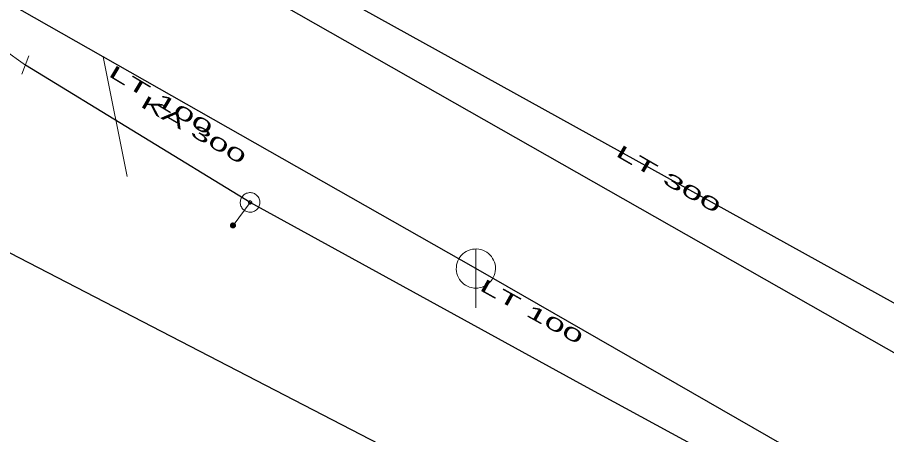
# Model space of a CAD drawing. Extents: x -687593 to -687108, y -975254 to -974717.
# Drawn here: x -687397.23 to -687352.84, y -974948.69 to -974927.39 of the extents above; entities that cross this region are included whole.
import ezdxf
from ezdxf.enums import TextEntityAlignment as Align

# ---------------------------------------------------------------- set-up
doc = ezdxf.new("R2010")
doc.units = 0
doc.header["$LTSCALE"] = 0.27
for name, color, linetype, lineweight in [('1', 7, 'Continuous', 25), ('11', 7, 'Continuous', 13), ('14', 7, 'Continuous', 13), ('17', 7, 'Continuous', 25), ('22', 7, 'Continuous', 13), ('34', 7, 'Continuous', 13), ('47', 7, 'Continuous', 13), ('9', 7, 'Continuous', 13)]:
    doc.layers.add(name, color=color, linetype=linetype, lineweight=lineweight)

msp = doc.modelspace()

# ---------------------------------------------------------------- linework, layer by layer
at = {"layer": '1'}
msp.add_lwpolyline([(-687190.553, -975166.941), (-687164.86, -975177.861), (-687155.924, -975158.837), (-687125.348, -975155.541), (-687124.826, -975139.621), (-687173.065, -975131.89), (-687231.828, -975028.025), (-687222.959, -975015.464), (-687237.898, -975004.026), (-687247.4, -975009.654), (-687276.892, -974983.781), (-687453.606, -974886.044), (-687460.232, -974860.45), (-687474.874, -974858.564), (-687482.889, -974882.272), (-687502.421, -974882.802), (-687499.452, -974907.164), (-687464.42, -974904.824), (-687331.319, -974973.728), (-687252.566, -975037.916), (-687192.379, -975151.48)], close=True, dxfattribs=at)
at = {"layer": '11'}
msp.add_line((-687391.62, -974935.51), (-687392.845, -974929.413), dxfattribs=at)
at = {"layer": '14'}
for p, q in [((-687396.817, -974929.825), (-687397.965, -974929.018)), ((-687385.348, -974936.838), (-687386.22, -974938.013))]:
    msp.add_line(p, q, dxfattribs=at)
at = {"layer": '14', "lineweight": 25}
msp.add_line((-687339.967, -974959.63), (-687373.818, -974940.214), dxfattribs=at)
msp.add_lwpolyline([(-687373.818, -974940.214), (-687392.845, -974929.413), (-687401.895, -974924.263)], dxfattribs=at)
at = {"layer": '17'}
for points in [[(-687435.81, -974897.134), (-687294.34, -974977.541), (-687214.33, -974877.654)], [(-687358.699, -974951.407), (-687368.317, -974946.193), (-687385.348, -974936.838), (-687396.817, -974929.825)]]:
    msp.add_lwpolyline(points, dxfattribs=at)
at = {"layer": '22'}
msp.add_line((-687373.818, -974942.214), (-687373.817, -974939.214), dxfattribs=at)
msp.add_lwpolyline([(-687372.818, -974940.214), (-687372.823, -974940.105), (-687372.841, -974939.997), (-687372.871, -974939.891), (-687372.911, -974939.79), (-687372.963, -974939.693), (-687373.025, -974939.603), (-687373.097, -974939.52), (-687373.177, -974939.446), (-687373.265, -974939.38), (-687373.359, -974939.325), (-687373.459, -974939.28), (-687373.564, -974939.247), (-687373.671, -974939.225), (-687373.78, -974939.215), (-687373.89, -974939.217), (-687373.998, -974939.231), (-687374.105, -974939.256), (-687374.208, -974939.293), (-687374.306, -974939.342), (-687374.398, -974939.4), (-687374.484, -974939.469), (-687374.561, -974939.546), (-687374.63, -974939.632), (-687374.689, -974939.724), (-687374.737, -974939.822), (-687374.774, -974939.925), (-687374.8, -974940.032), (-687374.814, -974940.14), (-687374.817, -974940.25), (-687374.807, -974940.359), (-687374.786, -974940.466), (-687374.752, -974940.57), (-687374.708, -974940.67), (-687374.653, -974940.765), (-687374.587, -974940.853), (-687374.513, -974940.933), (-687374.43, -974941.005), (-687374.34, -974941.067), (-687374.244, -974941.119), (-687374.142, -974941.16), (-687374.037, -974941.19), (-687373.929, -974941.208), (-687373.819, -974941.214), (-687373.71, -974941.208), (-687373.602, -974941.19), (-687373.497, -974941.161), (-687373.395, -974941.12), (-687373.298, -974941.068), (-687373.208, -974941.006), (-687373.125, -974940.935), (-687373.05, -974940.855), (-687372.985, -974940.767), (-687372.929, -974940.673), (-687372.885, -974940.573), (-687372.851, -974940.469), (-687372.829, -974940.361), (-687372.819, -974940.252)], close=True, dxfattribs=at)
at = {"layer": '34'}
msp.add_line((-687396.638, -974929.357), (-687396.996, -974930.291), dxfattribs=at)
at = {"layer": '47'}
for points in [[(-687384.924, -974937.104), (-687384.899, -974937.058), (-687384.878, -974937.01), (-687384.863, -974936.96), (-687384.853, -974936.909), (-687384.848, -974936.856), (-687384.849, -974936.804), (-687384.856, -974936.752), (-687384.867, -974936.701), (-687384.884, -974936.652), (-687384.905, -974936.604), (-687384.932, -974936.559), (-687384.964, -974936.517), (-687384.999, -974936.479), (-687385.039, -974936.445), (-687385.081, -974936.414), (-687385.127, -974936.389), (-687385.175, -974936.368), (-687385.226, -974936.353), (-687385.276, -974936.343), (-687385.329, -974936.338), (-687385.381, -974936.339), (-687385.434, -974936.345), (-687385.485, -974936.357), (-687385.534, -974936.373), (-687385.581, -974936.395), (-687385.626, -974936.422), (-687385.668, -974936.454), (-687385.706, -974936.489), (-687385.74, -974936.529), (-687385.771, -974936.571), (-687385.796, -974936.617), (-687385.817, -974936.665), (-687385.833, -974936.715), (-687385.842, -974936.766), (-687385.847, -974936.819), (-687385.847, -974936.871), (-687385.841, -974936.923), (-687385.829, -974936.974), (-687385.812, -974937.024), (-687385.79, -974937.071), (-687385.763, -974937.116), (-687385.732, -974937.158), (-687385.696, -974937.196), (-687385.656, -974937.23), (-687385.614, -974937.261), (-687385.568, -974937.286), (-687385.52, -974937.307), (-687385.471, -974937.322), (-687385.419, -974937.332), (-687385.366, -974937.337), (-687385.314, -974937.337), (-687385.263, -974937.33), (-687385.212, -974937.319), (-687385.162, -974937.301), (-687385.114, -974937.28), (-687385.069, -974937.253), (-687385.028, -974937.222), (-687384.989, -974937.186), (-687384.955, -974937.146)], [(-687385.278, -974936.881), (-687385.273, -974936.874), (-687385.271, -974936.866), (-687385.268, -974936.858), (-687385.266, -974936.85), (-687385.266, -974936.841), (-687385.266, -974936.832), (-687385.267, -974936.823), (-687385.268, -974936.815), (-687385.272, -974936.807), (-687385.275, -974936.799), (-687385.28, -974936.792), (-687385.285, -974936.785), (-687385.291, -974936.779), (-687385.296, -974936.773), (-687385.304, -974936.768), (-687385.311, -974936.763), (-687385.319, -974936.761), (-687385.327, -974936.758), (-687385.335, -974936.756), (-687385.344, -974936.756), (-687385.353, -974936.756), (-687385.362, -974936.757), (-687385.37, -974936.758), (-687385.379, -974936.761), (-687385.386, -974936.765), (-687385.393, -974936.77), (-687385.4, -974936.775), (-687385.406, -974936.781), (-687385.412, -974936.786), (-687385.417, -974936.794), (-687385.422, -974936.801), (-687385.424, -974936.809), (-687385.427, -974936.817), (-687385.429, -974936.825), (-687385.429, -974936.834), (-687385.43, -974936.842), (-687385.428, -974936.852), (-687385.427, -974936.86), (-687385.424, -974936.869), (-687385.42, -974936.876), (-687385.415, -974936.883), (-687385.41, -974936.89), (-687385.404, -974936.896), (-687385.399, -974936.902), (-687385.391, -974936.907), (-687385.384, -974936.912), (-687385.376, -974936.914), (-687385.368, -974936.917), (-687385.36, -974936.919), (-687385.351, -974936.919), (-687385.343, -974936.92), (-687385.333, -974936.918), (-687385.325, -974936.917), (-687385.317, -974936.913), (-687385.309, -974936.91), (-687385.302, -974936.905), (-687385.295, -974936.9), (-687385.289, -974936.894), (-687385.283, -974936.889)]]:
    msp.add_lwpolyline(points, close=True, dxfattribs=at)
at = {"layer": '9'}
for points in [[(-687386.346, -974938.013), (-687386.346, -974938.026), (-687386.343, -974938.039), (-687386.341, -974938.052), (-687386.336, -974938.064), (-687386.33, -974938.076), (-687386.323, -974938.087), (-687386.315, -974938.097), (-687386.304, -974938.107), (-687386.294, -974938.115), (-687386.284, -974938.122), (-687386.272, -974938.128), (-687386.26, -974938.133), (-687386.247, -974938.136), (-687386.233, -974938.138), (-687386.221, -974938.14), (-687386.208, -974938.139), (-687386.195, -974938.137), (-687386.182, -974938.134), (-687386.169, -974938.129), (-687386.157, -974938.123), (-687386.147, -974938.116), (-687386.137, -974938.108), (-687386.127, -974938.098), (-687386.119, -974938.088), (-687386.112, -974938.077), (-687386.106, -974938.065), (-687386.101, -974938.053), (-687386.098, -974938.04), (-687386.096, -974938.027), (-687386.093, -974938.014), (-687386.095, -974938.001), (-687386.097, -974937.988), (-687386.1, -974937.975), (-687386.105, -974937.963), (-687386.11, -974937.951), (-687386.118, -974937.94), (-687386.125, -974937.93), (-687386.136, -974937.92), (-687386.146, -974937.912), (-687386.157, -974937.905), (-687386.169, -974937.899), (-687386.181, -974937.894), (-687386.194, -974937.891), (-687386.206, -974937.889), (-687386.22, -974937.888), (-687386.233, -974937.888), (-687386.245, -974937.89), (-687386.259, -974937.893), (-687386.271, -974937.898), (-687386.282, -974937.904), (-687386.294, -974937.911), (-687386.304, -974937.919), (-687386.314, -974937.929), (-687386.321, -974937.939), (-687386.329, -974937.95), (-687386.335, -974937.962), (-687386.34, -974937.974), (-687386.343, -974937.987), (-687386.345, -974938)], [(-687386.326, -974938.013), (-687386.326, -974938.024), (-687386.325, -974938.035), (-687386.321, -974938.046), (-687386.318, -974938.056), (-687386.313, -974938.066), (-687386.307, -974938.075), (-687386.299, -974938.084), (-687386.292, -974938.092), (-687386.282, -974938.099), (-687386.274, -974938.105), (-687386.264, -974938.11), (-687386.254, -974938.114), (-687386.243, -974938.117), (-687386.232, -974938.12), (-687386.221, -974938.12), (-687386.21, -974938.12), (-687386.199, -974938.118), (-687386.188, -974938.115), (-687386.178, -974938.111), (-687386.168, -974938.106), (-687386.159, -974938.1), (-687386.15, -974938.093), (-687386.142, -974938.085), (-687386.135, -974938.076), (-687386.129, -974938.067), (-687386.124, -974938.057), (-687386.12, -974938.047), (-687386.117, -974938.036), (-687386.115, -974938.025), (-687386.114, -974938.014), (-687386.114, -974938.003), (-687386.115, -974937.992), (-687386.119, -974937.981), (-687386.123, -974937.971), (-687386.128, -974937.961), (-687386.134, -974937.952), (-687386.141, -974937.943), (-687386.149, -974937.935), (-687386.157, -974937.928), (-687386.167, -974937.922), (-687386.177, -974937.917), (-687386.186, -974937.913), (-687386.198, -974937.91), (-687386.208, -974937.908), (-687386.22, -974937.908), (-687386.231, -974937.907), (-687386.242, -974937.909), (-687386.253, -974937.912), (-687386.262, -974937.916), (-687386.272, -974937.921), (-687386.282, -974937.927), (-687386.291, -974937.934), (-687386.299, -974937.942), (-687386.306, -974937.951), (-687386.311, -974937.96), (-687386.316, -974937.97), (-687386.321, -974937.98), (-687386.324, -974937.991), (-687386.326, -974938.002)], [(-687386.307, -974938.013), (-687386.307, -974938.022), (-687386.306, -974938.031), (-687386.303, -974938.04), (-687386.299, -974938.048), (-687386.296, -974938.056), (-687386.291, -974938.064), (-687386.284, -974938.071), (-687386.279, -974938.077), (-687386.272, -974938.083), (-687386.264, -974938.088), (-687386.255, -974938.092), (-687386.248, -974938.095), (-687386.239, -974938.098), (-687386.23, -974938.099), (-687386.221, -974938.101), (-687386.212, -974938.1), (-687386.203, -974938.099), (-687386.194, -974938.096), (-687386.186, -974938.093), (-687386.178, -974938.089), (-687386.169, -974938.084), (-687386.163, -974938.078), (-687386.157, -974938.072), (-687386.151, -974938.065), (-687386.146, -974938.057), (-687386.142, -974938.049), (-687386.139, -974938.041), (-687386.136, -974938.032), (-687386.135, -974938.023), (-687386.132, -974938.014), (-687386.134, -974938.005), (-687386.135, -974937.996), (-687386.137, -974937.987), (-687386.141, -974937.979), (-687386.145, -974937.971), (-687386.15, -974937.963), (-687386.156, -974937.956), (-687386.162, -974937.95), (-687386.169, -974937.944), (-687386.177, -974937.939), (-687386.184, -974937.935), (-687386.193, -974937.932), (-687386.201, -974937.929), (-687386.211, -974937.928), (-687386.22, -974937.927), (-687386.228, -974937.927), (-687386.238, -974937.928), (-687386.247, -974937.931), (-687386.255, -974937.934), (-687386.262, -974937.938), (-687386.271, -974937.943), (-687386.277, -974937.949), (-687386.284, -974937.955), (-687386.289, -974937.962), (-687386.294, -974937.97), (-687386.299, -974937.978), (-687386.302, -974937.986), (-687386.304, -974937.995), (-687386.306, -974938.004)], [(-687386.287, -974938.013), (-687386.287, -974938.02), (-687386.286, -974938.027), (-687386.284, -974938.034), (-687386.282, -974938.04), (-687386.279, -974938.046), (-687386.275, -974938.052), (-687386.271, -974938.058), (-687386.266, -974938.063), (-687386.26, -974938.067), (-687386.254, -974938.071), (-687386.248, -974938.074), (-687386.242, -974938.077), (-687386.235, -974938.078), (-687386.228, -974938.081), (-687386.221, -974938.081), (-687386.213, -974938.081), (-687386.206, -974938.079), (-687386.2, -974938.078), (-687386.194, -974938.075), (-687386.186, -974938.072), (-687386.182, -974938.068), (-687386.176, -974938.064), (-687386.171, -974938.059), (-687386.167, -974938.053), (-687386.163, -974938.047), (-687386.159, -974938.041), (-687386.157, -974938.035), (-687386.155, -974938.028), (-687386.154, -974938.021), (-687386.152, -974938.014), (-687386.152, -974938.007), (-687386.154, -974938), (-687386.156, -974937.993), (-687386.159, -974937.987), (-687386.162, -974937.98), (-687386.166, -974937.975), (-687386.169, -974937.969), (-687386.174, -974937.964), (-687386.181, -974937.96), (-687386.186, -974937.956), (-687386.193, -974937.953), (-687386.199, -974937.95), (-687386.206, -974937.948), (-687386.213, -974937.947), (-687386.22, -974937.947), (-687386.227, -974937.947), (-687386.233, -974937.947), (-687386.24, -974937.949), (-687386.247, -974937.952), (-687386.253, -974937.955), (-687386.259, -974937.959), (-687386.265, -974937.963), (-687386.27, -974937.968), (-687386.274, -974937.974), (-687386.277, -974937.979), (-687386.281, -974937.986), (-687386.284, -974937.992), (-687386.284, -974937.999), (-687386.287, -974938.006)], [(-687386.267, -974938.013), (-687386.267, -974938.018), (-687386.267, -974938.023), (-687386.266, -974938.028), (-687386.264, -974938.032), (-687386.262, -974938.037), (-687386.259, -974938.041), (-687386.255, -974938.044), (-687386.252, -974938.048), (-687386.249, -974938.051), (-687386.245, -974938.054), (-687386.24, -974938.056), (-687386.235, -974938.058), (-687386.231, -974938.059), (-687386.226, -974938.061), (-687386.221, -974938.061), (-687386.216, -974938.061), (-687386.211, -974938.06), (-687386.206, -974938.059), (-687386.201, -974938.057), (-687386.196, -974938.055), (-687386.193, -974938.052), (-687386.189, -974938.049), (-687386.186, -974938.045), (-687386.183, -974938.042), (-687386.179, -974938.038), (-687386.178, -974938.033), (-687386.176, -974938.029), (-687386.174, -974938.024), (-687386.174, -974938.019), (-687386.173, -974938.014), (-687386.173, -974938.009), (-687386.174, -974938.004), (-687386.174, -974937.999), (-687386.177, -974937.995), (-687386.179, -974937.99), (-687386.182, -974937.986), (-687386.184, -974937.982), (-687386.188, -974937.979), (-687386.191, -974937.976), (-687386.196, -974937.973), (-687386.201, -974937.971), (-687386.205, -974937.969), (-687386.21, -974937.968), (-687386.215, -974937.967), (-687386.22, -974937.967), (-687386.225, -974937.967), (-687386.23, -974937.968), (-687386.235, -974937.968), (-687386.239, -974937.97), (-687386.244, -974937.972), (-687386.248, -974937.975), (-687386.25, -974937.978), (-687386.255, -974937.981), (-687386.257, -974937.985), (-687386.261, -974937.989), (-687386.262, -974937.994), (-687386.265, -974937.998), (-687386.266, -974938.003), (-687386.267, -974938.008)], [(-687386.247, -974938.013), (-687386.247, -974938.016), (-687386.248, -974938.019), (-687386.247, -974938.021), (-687386.245, -974938.024), (-687386.245, -974938.027), (-687386.243, -974938.029), (-687386.24, -974938.031), (-687386.239, -974938.033), (-687386.237, -974938.035), (-687386.235, -974938.037), (-687386.232, -974938.039), (-687386.228, -974938.04), (-687386.227, -974938.04), (-687386.223, -974938.041), (-687386.221, -974938.041), (-687386.218, -974938.041), (-687386.215, -974938.041), (-687386.212, -974938.04), (-687386.21, -974938.039), (-687386.206, -974938.038), (-687386.205, -974938.036), (-687386.201, -974938.034), (-687386.2, -974938.032), (-687386.199, -974938.03), (-687386.196, -974938.028), (-687386.196, -974938.025), (-687386.194, -974938.022), (-687386.194, -974938.02), (-687386.193, -974938.017), (-687386.191, -974938.014), (-687386.193, -974938.011), (-687386.193, -974938.008), (-687386.194, -974938.005), (-687386.195, -974938.003), (-687386.196, -974938), (-687386.198, -974937.998), (-687386.199, -974937.995), (-687386.201, -974937.993), (-687386.204, -974937.992), (-687386.206, -974937.99), (-687386.208, -974937.989), (-687386.211, -974937.988), (-687386.213, -974937.987), (-687386.217, -974937.987), (-687386.22, -974937.986), (-687386.223, -974937.987), (-687386.226, -974937.986), (-687386.228, -974937.988), (-687386.231, -974937.988), (-687386.233, -974937.989), (-687386.235, -974937.991), (-687386.238, -974937.992), (-687386.24, -974937.994), (-687386.242, -974937.997), (-687386.244, -974937.999), (-687386.245, -974938.002), (-687386.245, -974938.004), (-687386.247, -974938.007), (-687386.247, -974938.01)], [(-687386.228, -974938.013), (-687386.228, -974938.015), (-687386.228, -974938.015), (-687386.227, -974938.015), (-687386.227, -974938.017), (-687386.228, -974938.018), (-687386.226, -974938.018), (-687386.226, -974938.018), (-687386.226, -974938.02), (-687386.226, -974938.02), (-687386.225, -974938.021), (-687386.223, -974938.021), (-687386.223, -974938.021), (-687386.223, -974938.022), (-687386.221, -974938.022), (-687386.221, -974938.022), (-687386.22, -974938.022), (-687386.218, -974938.022), (-687386.218, -974938.021), (-687386.218, -974938.021), (-687386.216, -974938.021), (-687386.216, -974938.02), (-687386.216, -974938.02), (-687386.215, -974938.019), (-687386.215, -974938.019), (-687386.213, -974938.018), (-687386.213, -974938.017), (-687386.212, -974938.016), (-687386.212, -974938.016), (-687386.212, -974938.015), (-687386.212, -974938.014), (-687386.212, -974938.013), (-687386.212, -974938.012), (-687386.212, -974938.012), (-687386.213, -974938.011), (-687386.213, -974938.01), (-687386.213, -974938.009), (-687386.213, -974938.009), (-687386.215, -974938.008), (-687386.215, -974938.008), (-687386.216, -974938.007), (-687386.217, -974938.007), (-687386.218, -974938.006), (-687386.218, -974938.006), (-687386.218, -974938.006), (-687386.22, -974938.006), (-687386.221, -974938.006), (-687386.222, -974938.006), (-687386.222, -974938.006), (-687386.223, -974938.007), (-687386.223, -974938.006), (-687386.225, -974938.008), (-687386.225, -974938.008), (-687386.226, -974938.008), (-687386.226, -974938.008), (-687386.227, -974938.01), (-687386.227, -974938.011), (-687386.227, -974938.012), (-687386.228, -974938.012), (-687386.228, -974938.013)]]:
    msp.add_lwpolyline(points, close=True, dxfattribs=at)

# ---------------------------------------------------------------- texts
at = {"layer": '1'}
for s, rotation, width, p in [('LT 100', 329, 2.15, (-687390.0767, -974931.8934)), ('LT 100', 329, 2.15, (-687390.0767, -974931.8934)), ('LT 100', 329, 2.15, (-687390.0767, -974931.8934)), ('LT 100', 329, 2.15, (-687390.0767, -974931.8934)), ('LT 100', 329, 2.15, (-687390.0767, -974931.8934)), ('KA 300', 330, 2.05, (-687388.4027, -974933.4189)), ('KA 300', 330, 2.05, (-687388.4027, -974933.4189)), ('KA 300', 330, 2.05, (-687388.4027, -974933.4189)), ('KA 300', 330, 2.05, (-687388.4027, -974933.4189)), ('KA 300', 330, 2.05, (-687388.4027, -974933.4189)), ('LT 300', 330, 2.15, (-687364.1487, -974935.9279)), ('LT 300', 330, 2.15, (-687364.1487, -974935.9279)), ('LT 300', 330, 2.15, (-687364.1487, -974935.9279)), ('LT 300', 330, 2.15, (-687364.1487, -974935.9279)), ('LT 300', 330, 2.15, (-687364.1487, -974935.9279)), ('LT 100', 331, 2.1, (-687371.1356, -974942.7013)), ('LT 100', 331, 2.1, (-687371.1356, -974942.7013)), ('LT 100', 331, 2.1, (-687371.1356, -974942.7013)), ('LT 100', 331, 2.1, (-687371.1356, -974942.7013)), ('LT 100', 331, 2.1, (-687371.1356, -974942.7013))]:
    msp.add_text(s, height=0.6667, rotation=rotation, dxfattribs=dict(at, width=width)).set_placement(p, align=Align.CENTER)

doc.saveas('drawing.dxf')
